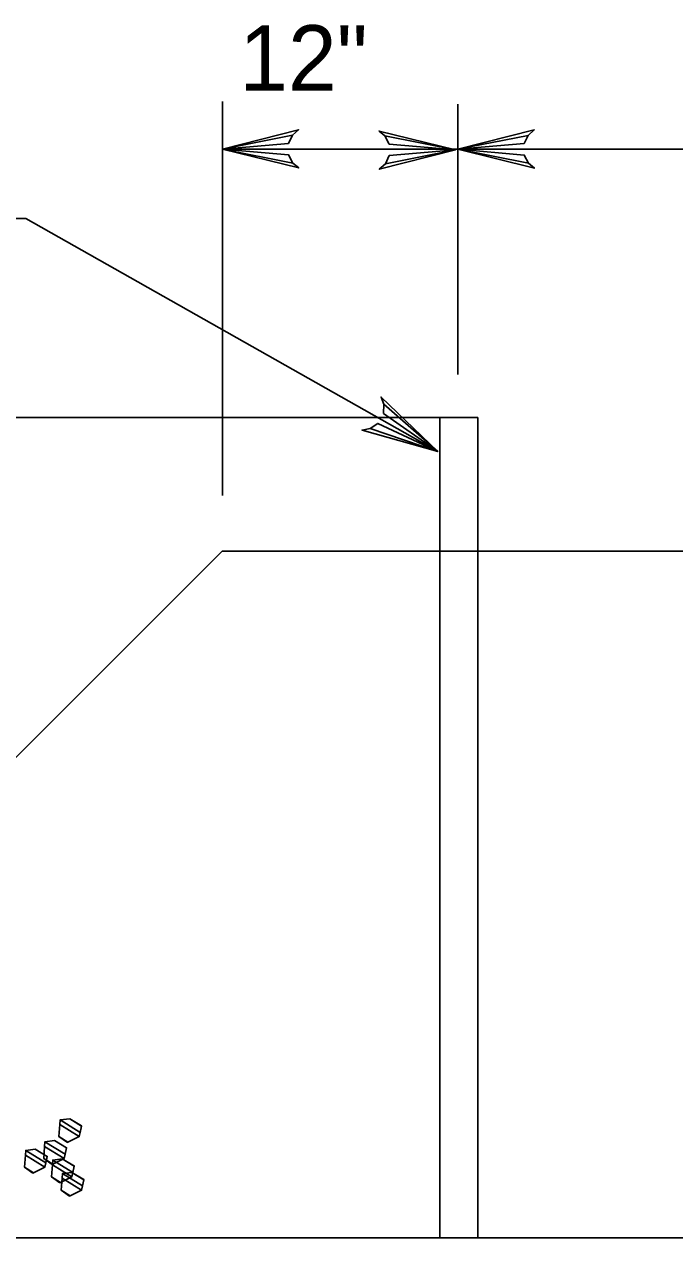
# Model space of a CAD drawing. Extents: x 636462 to 639049, y 299944 to 300538.
# Drawn here: x 637718.9 to 637748.7, y 300291.8 to 300347.3 of the extents above; entities that cross this region are included whole.
import ezdxf

# ---------------------------------------------------------------- set-up
doc = ezdxf.new("R2010")
doc.units = 0
doc.layers.add('Default', color=7, linetype='Continuous')

msp = doc.modelspace()

# ---------------------------------------------------------------- linework, layer by layer
at = {"layer": 'Default'}
for p, q in [((637727.966, 300325.747), (637727.966, 300343.803)), ((637738.758, 300331.289), (637738.758, 300343.675)), ((637727.966, 300341.611), (637810.097, 300341.611)), ((637715.459, 300338.433), (637718.957, 300338.433)), ((637737.835, 300327.764), (637718.957, 300338.433)), ((637684.462, 300329.325), (637739.67, 300329.325)), ((637737.921, 300329.325), (637737.921, 300323.205)), ((637739.67, 300329.325), (637739.67, 300323.205)), ((637696.5, 300291.751), (637727.952, 300323.205)), ((637727.952, 300323.205), (637810.14, 300323.205)), ((637737.921, 300323.205), (637737.921, 300291.751)), ((637739.67, 300323.205), (637739.67, 300291.751)), ((637685.207, 300291.751), (637853.724, 300291.751))]:
    msp.add_line(p, q, dxfattribs=at)
for points in [[(637731.196, 300340.981), (637731.465, 300340.758), (637727.964, 300341.618), (637731.196, 300340.981), (637731, 300341.354), (637727.964, 300341.618), (637730.993, 300341.878), (637731.176, 300342.253), (637727.964, 300341.618), (637731.458, 300342.507), (637731.176, 300342.253)], [(637735.41, 300342.22), (637735.141, 300342.444), (637738.642, 300341.583), (637735.41, 300342.22), (637735.607, 300341.847), (637738.642, 300341.583), (637735.613, 300341.324), (637735.431, 300340.948), (637738.642, 300341.583), (637735.148, 300340.695), (637735.431, 300340.948)], [(637741.99, 300340.973), (637742.259, 300340.75), (637738.758, 300341.611), (637741.99, 300340.973), (637741.794, 300341.346), (637738.758, 300341.611), (637741.787, 300341.87), (637741.97, 300342.245), (637738.758, 300341.611), (637742.252, 300342.499), (637741.97, 300342.245)], [(637735.357, 300329.934), (637735.235, 300330.262), (637737.835, 300327.764), (637735.357, 300329.934), (637735.34, 300329.513), (637737.835, 300327.764), (637735.083, 300329.056), (637734.737, 300328.823), (637737.835, 300327.764), (637734.366, 300328.745), (637734.737, 300328.823)]]:
    msp.add_lwpolyline(points, dxfattribs=at)
for points in [[(637720.518, 300296.935), (637721.409, 300296.383), (637721.453, 300296.579), (637720.533, 300297.149)], [(637720.533, 300297.149), (637721.453, 300296.579), (637721.517, 300296.869), (637720.976, 300297.204)], [(637720.976, 300297.204), (637721.517, 300296.869), (637721.518, 300296.872), (637721.518, 300296.872)], [(637720.479, 300296.383), (637720.892, 300296.126), (637721.409, 300296.383), (637720.518, 300296.935)], [(637719.823, 300295.934), (637720.717, 300295.38), (637720.761, 300295.578), (637719.838, 300296.15)], [(637719.838, 300296.15), (637720.761, 300295.578), (637720.825, 300295.866), (637720.279, 300296.205)], [(637720.279, 300296.205), (637720.825, 300295.866), (637720.827, 300295.875), (637720.827, 300295.875)], [(637720.863, 300296.112), (637720.863, 300296.112), (637720.892, 300296.126), (637720.479, 300296.383)], [(637718.901, 300294.979), (637719.314, 300294.723), (637719.83, 300294.979), (637718.94, 300295.531)], [(637718.94, 300295.531), (637719.83, 300294.979), (637719.874, 300295.18), (637718.956, 300295.75)], [(637718.956, 300295.75), (637719.874, 300295.18), (637719.938, 300295.465), (637719.391, 300295.804)], [(637719.391, 300295.804), (637719.938, 300295.465), (637719.941, 300295.477), (637719.941, 300295.477)], [(637719.787, 300295.38), (637720.198, 300295.125), (637720.717, 300295.38), (637719.823, 300295.934)], [(637719.283, 300294.708), (637719.283, 300294.708), (637719.314, 300294.723), (637718.901, 300294.979)], [(637720.165, 300295.109), (637720.165, 300295.109), (637720.198, 300295.125), (637719.787, 300295.38)], [(637720.139, 300294.54), (637720.554, 300294.283), (637721.069, 300294.54), (637720.177, 300295.094)], [(637720.177, 300295.094), (637721.069, 300294.54), (637721.115, 300294.738), (637720.192, 300295.311)], [(637720.192, 300295.311), (637721.115, 300294.738), (637721.182, 300295.024), (637720.63, 300295.366)], [(637720.63, 300295.366), (637721.182, 300295.024), (637721.185, 300295.036), (637721.185, 300295.036)], [(637720.523, 300294.267), (637720.523, 300294.267), (637720.554, 300294.283), (637720.139, 300294.54)], [(637720.582, 300293.924), (637720.997, 300293.666), (637721.512, 300293.924), (637720.623, 300294.475)], [(637720.623, 300294.475), (637721.512, 300293.924), (637721.557, 300294.123), (637720.639, 300294.692)], [(637720.639, 300294.692), (637721.557, 300294.123), (637721.62, 300294.403), (637721.073, 300294.743)], [(637721.073, 300294.743), (637721.62, 300294.403), (637721.623, 300294.417), (637721.623, 300294.417)], [(637720.966, 300293.651), (637720.966, 300293.651), (637720.997, 300293.666), (637720.582, 300293.924)]]:
    msp.add_lwpolyline(points, close=True, dxfattribs=at)

# ---------------------------------------------------------------- texts
msp.add_text('12"', height=2.998, dxfattribs=at).set_placement((637728.743, 300344.294))

doc.saveas('drawing.dxf')
